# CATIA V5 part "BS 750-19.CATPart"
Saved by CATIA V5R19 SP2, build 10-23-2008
Part number: BS 750-19
Bounding box of the stored display mesh (mm): x -22.494 to 22.494, y -22.494 to 22.494, z 0 to 70
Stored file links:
  C:\Users\Bora\Desktop\3D Katı model\BS serisi\BS 750\BS 750-19.CATPart
  C:\Program Files\Dassault Systemes\B19\intel_a\reffiles\standard\MetricThickPitch.txt
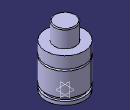
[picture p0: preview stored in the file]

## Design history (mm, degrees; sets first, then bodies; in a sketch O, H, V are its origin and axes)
Body1 (main body)
  Sketch1 on yz-plane, origin (0, 0, 0), H (0, 1, 0), V (0, 0, 1)
    point P3 (12.5, 69)
    point P5 (12.5, 69)
    point P7 (22.5, 36.5)
    point P8 (22.5, 34.5)
    point P12 (22.5, 34.5)
    point P13 (22.5, 36.5)
    line L1 (22.5, 0) -> (22.5, 4)
    line L2 (12.5, 69) -> (12.5, 50)
    arc A1 centre (11.5, 69) radius 1 from (12.5, 69) to (11.5, 70) ccw
    arc A2 centre (22.5, 35.5) radius 1 from (22.5, 36.5) to (22.5, 34.5) ccw
    line L3 (20, 7.5) -> (20, 4)
    line L4 (22.5, 7.5) -> (22.5, 34.5)
    line L5 (22.5, 36.5) -> (22.5, 50)
    line L6 (11.5, 70) -> (0, 70)
    point P15 (0, 70)
    line L7 (12.5, 50) -> (22.5, 50)
    line L8 (20, 7.5) -> (22.5, 7.5)
    line L9 (20, 4) -> (22.5, 4)
    line L10 (0, 0) -> (22.5, 0)
    coincidence: P15 V, P3 P5, P7 P13, P8 P12
    tangency: L6 A1
    horizontal: L7 H, L8 H, L9 H, L10 H
  Shaft1: profile Sketch1, axis Sketch1.V, angle 360
  Sketch2 on face of Shaft1 from Sketch1.L10, origin (0, 0, 0), H (1, 0, 0), V (0, -1, 0)
    point P1 (10, 0)
    distance P1 V = 10
  Hole1: placed by Sketch2, at (10, 0, 0) direction (0, 0, 1), diameter 6.647, depth 4, threaded "M8", thread diameter 8, thread depth 4, pitch 1.25
  CircPattern1: of Hole1, instances 2, angular step 180, axis from xy-plane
